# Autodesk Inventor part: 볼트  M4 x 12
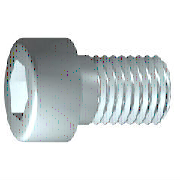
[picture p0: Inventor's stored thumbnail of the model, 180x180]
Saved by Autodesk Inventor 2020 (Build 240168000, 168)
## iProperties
Created: 2015-12
Part Number: 볼트  M4 x 12
Material: 스테인리스강
Description: 6각머리 태핑 나사
Document SubType Name: Modeling
Standard: KS B 1003
Designer: mdu
Standards Organization: KS
Language: ko-KR
Size Designation: M 4 x 12
Categories: <MemberInstance><Categories><Category DisplayName="조임쇠" InternalName="e4da775c-781d-43d5-af7c-5136215cf5a6" Mnemonic="FSTN"><Category DisplayName="볼트" InternalN
Density: 1 g/cm^3
Mass: 0.284306 g
Surface Area: 3.30853 cm^2
Volume: 0.284306 cm^3
Appearance: 반광택
IsCustomPart: 0
Author: mdu
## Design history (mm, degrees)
sketch "스케치1"
  geometry: L1 (-1, 0)-(10, 0); L2 (10, 0)-(10, 2); L3 (10, 2)-(1.75, 2); L4 (1.75, 2)-(1.32, 2); L5 (1.32, 2)-(0, 2); L6 (0, 2)-(0, 3.5); L7 (0, 3.5)-(-4, 3.5); L8 (-4, 3.5)-(-4, 1.732); L9 (-4, 1.732)-(-2, 1.732); L10 (-2, 1.732)-(-1, 0); L11 (-7.2, 0)-(15.2, 0) reference; L12 (0, -0.7)-(0, 4.2) reference; L13 (1.75, 2)-(0, 2)
  constraints: 22 end point, 6 parallel, 2 collinear, 2 perpendicular, 1 horizontal, 1 point on line
  dimensions: "d1" = 8.25 distance from line of L3.end L2 (= GEL); "d2" = 0.42952 distance of L4.end L3.end (computed from GAL); "d3" = 4 distance between parallel lines of L8 L6 (= KOH); "d4" = 2 distance of L8.end L9.end (= INTI); "d5" = 60 deg angle of L10 L1; "d6" = 4 diameter of L3 L1 (= GD); "d7" = 4 diameter of L5 L1 (= BDM); "d8" = 3.4641 diameter of L9 L1 (= 1.1547 x SW); "d9" = 7 diameter of L7 L1 (= KOD); "d26" = 10 distance between parallel lines of L12 L2 (= NLG)
revolve "본체" sketch "스케치1" stored, may be unused: angle "d10" = 90 deg
sketch "스케치2"
  geometry: L1 (0, -4.9)-(0, 4.9) reference; L2 (-4.9, 0)-(4.9, 0) reference; L3 (1.732, 0)-(0.866, -1.5); L4 (0.866, -1.5)-(-0.866, -1.5); L5 (-0.866, -1.5)-(-1.732, 0); L6 (-1.732, 0)-(-0.866, 1.5); L7 (-0.866, 1.5)-(0.866, 1.5); L8 (0.866, 1.5)-(1.732, 0); 2 further points
  constraints: 12 end point, 1 coincident, 1 horizontal alignment, 1 point on line, 12 other
extrude "슬롯" join sketch "스케치2" stored distance "d11" = 10; taper "d12" = 0 deg
workplane "Work Plane1"
fillet "Fillet2" dims "d30" = 0.1 (= R)
body "Solid1"
fillet "모깎기1" dims "d17" = 0.4 (= RR)
feature "스레드" dims "d13" = 8.25 (= GEL), "d14" = 0
chamfer "모따기1" distance "d15" = 0.42941 (= -0.5 x SPD + 0.5 x GD); stored, may be unused: second distance "d16" = 0.42941 (= GUL), angle "d27" = 45 deg
other parameters: "GD" = 4 (= NND) [user parameter; used in 2 equation terms], "NLG" = 10 [user parameter; used in 1 equation term], "GEL" = 8.25 [user parameter; used in 2 equation terms], "KOD" = 7 [user parameter; used in 1 equation term], "KOH" = 4 [user parameter; used in 1 equation term], "INTI" = 2 [user parameter; used in 1 equation term], "GAL" = 0.42941 (= 0.61345 x PTC) [user parameter; used in 1 equation term], "GUL" = 0.42941 (= 0.61345 x PTC) [user parameter; used in 1 equation term], "BDM" = 4 (= NND) [user parameter; used in 1 equation term], "SW" = 3 [user parameter; used in 2 equation terms], "RR" = 0.4 [user parameter; used in 1 equation term], "SPD" = 3.14117 (= NND - 1.2269 x PTC) [user parameter; used in 1 equation term], "d19" = 0, "d28" = 0, "d29" = 0, "R" = 0.1 [user parameter; used in 1 equation term], "PHH" = 0.2 [user parameter], "GD1" = 3.14117 (= THREADDIA - 1.2269 x PTC) [user parameter], "THREADDIA" = 4 [user parameter; used in 1 equation term], "FAWI" = 45 deg [user parameter], "TPU" = 14.28571 (computed from PTC) [user parameter], "PTC" = 0.7 [user parameter; used in 5 equation terms], "NND" = 4 [user parameter; used in 3 equation terms], "TOA" = 30 deg [user parameter], "E0" = 3.465 (= 1.155 x SW) [user parameter]
